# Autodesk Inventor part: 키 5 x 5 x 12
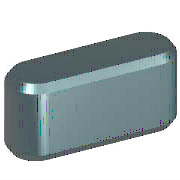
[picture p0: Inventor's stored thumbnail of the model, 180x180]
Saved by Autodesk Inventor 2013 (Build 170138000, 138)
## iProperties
IsCustomPart: 1
Created: 2012-02
Part Number: 키 5 x 5 x 12
Material: 강철, 연강
Description: 키 및 해당 키홈
Document SubType Name: Modeling
Standard: KS B 1311
Designer: mduedu
Standards Organization: KS
Language: ko-KR
Size Designation: 5 x 5 x 12
Categories: <MemberInstance><Categories><Category DisplayName="샤프트 부품" InternalName="7f7aeb1f-a693-4053-b835-cee3144e0d98" Mnemonic="SHFT"><Category DisplayName="키" Interna
Density: 7.86 g/cm^3
Mass: 2.11085 g
Surface Area: 2.43471 cm^2
Volume: 0.268556 cm^3
Author: mduedu
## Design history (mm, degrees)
workplane "Work Plane1"
workplane "Work Plane2"
sketch "스케치1"
  geometry: L1 (2.5, 2.5)-(9.5, 2.5); L2 (9.5, -2.5)-(2.5, -2.5); L3 (0, 9.4)-(0, -7.4) reference; L4 (-5, 0)-(30, 0) reference; L5 (12, 0)-(12, 7); A1 r 2.5 centre (2.5, 0) between (2.5, 2.5) and (2.5, -2.5); A2 r 2.5 centre (9.5, 0) between (9.5, -2.5) and (9.5, 2.5)
  constraints: 6 end point, 5 point on circle, 4 tangent, 3 point on line, 2 centre point, 1 horizontal, 1 parallel, 1 perpendicular
  dimensions: "d0" = 2.5 radius of A1 (= 0.5 x PB); "d13" = 2.5 radius of A2 (= 0.5 x PB); "d14" = 12 distance between parallel lines of L5 L3 (= NLG)
extrude "본체1" new body sketch "스케치1" taper "d3" = 0 deg; stored distance "d4" = 10
workplane "Work Plane3"
body "Solid1"
chamfer "모따기1" distance "d8" = 0.4 (= PHH); stored, may be unused: second distance "d9" = 0.4 (= PHH), angle "d15" = 45 deg
other parameters: "d1" = -3 (= -PNT), "d2" = 2 (= PH - PNT), "NLG" = 12 [user parameter; used in 3 equation terms], "PB" = 5 [user parameter; used in 2 equation terms], "PNT" = 3 [user parameter; used in 2 equation terms], "PH" = 5 [user parameter; used in 1 equation term], "PHH" = 0.4 [user parameter; used in 2 equation terms], "d10" = 0, "d16" = 0, "d17" = 0, "d18" = 0, "WDMIN" = 12 [user parameter], "PLB2" = 12 (= NLG) [user parameter], "WDMAX" = 17 [user parameter], "PLB1" = 12 (= NLG) [user parameter], "RR" = 0.16 [user parameter], "PUEB" = 2.3 [user parameter]
